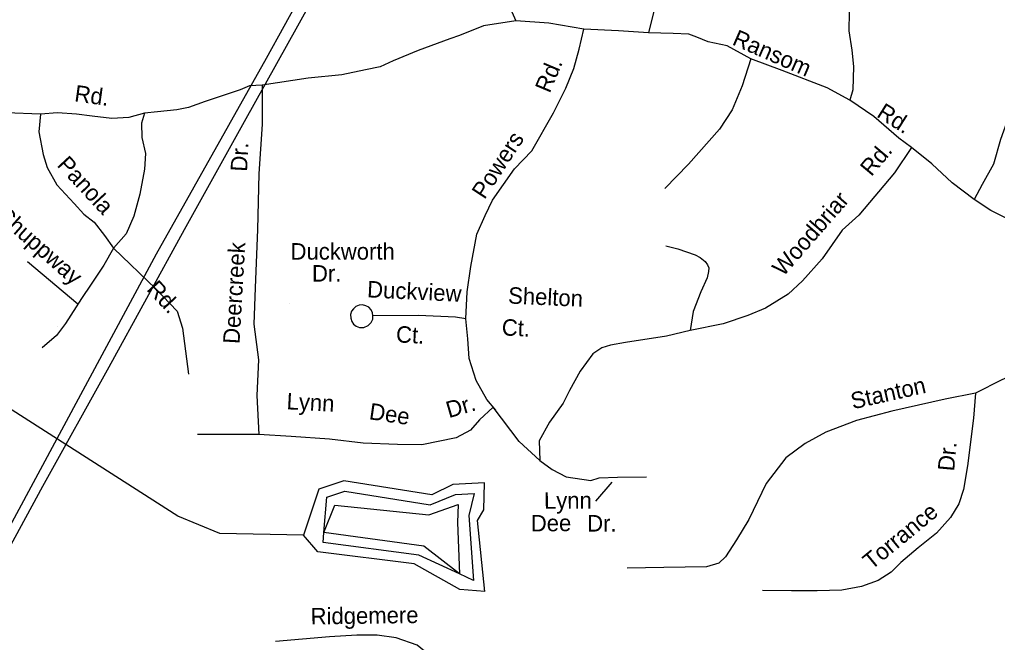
# Model space of a CAD drawing. Extents: x 1551653 to 1702041, y 811336 to 920032.
# Drawn here: x 1610530 to 1614421, y 869748 to 872227 of the extents above; entities that cross this region are included whole.
import ezdxf

# ---------------------------------------------------------------- set-up
doc = ezdxf.new("R2010")
doc.units = 0
for name, color, linetype in [('Old_Level_10', 7, 'Continuous'), ('Old_Level_35', 7, 'Continuous'), ('Old_Level_56', 7, 'Continuous'), ('Old_Level_59', 7, 'Continuous'), ('Old_Level_60', 7, 'Continuous'), ('Old_Level_61', 7, 'Continuous')]:
    doc.layers.add(name, color=color, linetype=linetype)

msp = doc.modelspace()

# ---------------------------------------------------------------- linework, layer by layer
at = {"layer": 'Old_Level_10'}
for p, q in [((1611603.332, 871098.796), (1611603.332, 871098.796)), ((1610680.284, 871003.858), (1610680.284, 871003.858)), ((1612886.473, 870386.234), (1612822.266, 870310.292))]:
    msp.add_line(p, q, dxfattribs=at)
at = {"layer": 'Old_Level_35'}
for p, q in [((1610561.396, 871264.534), (1610762.54, 871095.452)), ((1611481.947, 870576.219), (1611238.347, 870576.219))]:
    msp.add_line(p, q, dxfattribs=at)
for points in [[(1612696.66, 873710.891), (1612676.28, 873663.076), (1612635.886, 873605.461), (1612595.335, 873549.851), (1612572.789, 873494.077), (1612568.537, 873452.138), (1612587.848, 873388.109), (1612637.002, 873305.662), (1612714.285, 873218.841), (1612805.21, 873114.134), (1612913.769, 872971.047), (1612994.688, 872856.335), (1613053.799, 872751.874), (1613094.458, 872625.572), (1613121.564, 872531.366), (1613127.066, 872477.222), (1613110.81, 872435.526), (1613084.304, 872391.638), (1613059.963, 872345.907), (1613053.215, 872259.992), (1613033.074, 872174.752)], [(1613905.739, 872379.958), (1613873.761, 872372.203), (1613857.518, 872360.526), (1613835.336, 872322.754), (1613830.595, 872256.809), (1613829.893, 872182.78), (1613841.313, 872104.703), (1613848.62, 872040.717), (1613845.71, 871946.718), (1613833.238, 871906.48)], [(1612463.113, 872316.053), (1612504.818, 872222.195)], [(1612504.818, 872222.195), (1612376.121, 872201.792), (1612280.323, 872163.444), (1612242.004, 872149.748), (1612116.904, 872103.506), (1612016.612, 872062.518), (1611964.506, 872038.962), (1611906.442, 872027.535), (1611812.281, 872007.314), (1611678.164, 871993.618), (1611495.609, 871966.557)], [(1612775.42, 872189.191), (1612635.614, 872212.643), (1612504.818, 872222.195)], [(1612305.81, 871036.392), (1612311.47, 871144.025), (1612326.303, 871243.782), (1612349.604, 871373.305), (1612382.904, 871447.676), (1612412.356, 871508.516), (1612500.143, 871633.522), (1612568.058, 871704.31), (1612654.397, 871856.449), (1612703.202, 871953.916), (1612736.001, 872031.695), (1612756.591, 872109.526), (1612775.42, 872189.191)], [(1613033.074, 872174.752), (1612913.153, 872181.99), (1612775.42, 872189.191)], [(1613439.098, 872070.828), (1613346.036, 872122.872), (1613270.475, 872138.509), (1613224.825, 872157.049), (1613192.854, 872169.303), (1613130.869, 872171.763), (1613033.074, 872174.752)], [(1613439.098, 872070.828), (1613404.795, 871963.28), (1613366.029, 871867.61), (1613315.229, 871790.196), (1613192.142, 871651.41), (1613097.316, 871554.278)], [(1613833.238, 871906.48), (1613742.914, 871955.784), (1613565.003, 872024.263), (1613439.098, 872070.828)], [(1611495.609, 871966.557), (1611445.512, 871963.488), (1611408.199, 871947.053), (1611269.112, 871900.949)], [(1611495.609, 871966.557), (1611495.609, 871810.427), (1611481.924, 871613.21), (1611476.449, 871391.34), (1611468.262, 871159.653), (1611462.788, 871014.479), (1611481.624, 870872.521), (1611474.341, 870730.586), (1611481.947, 870576.219)], [(1611269.112, 871900.949), (1611202.8, 871877.682), (1611156.387, 871867.619), (1611079.748, 871859.401), (1611027.218, 871854.077)], [(1614078.347, 871717.98), (1614028.219, 871755.417), (1613929.036, 871840.741), (1613833.238, 871906.48)], [(1610613.498, 871850.074), (1610477.728, 871855.232), (1610437.508, 871845.645), (1610367.354, 871810.448), (1610198.253, 871692.01), (1610083.585, 871613.09), (1610017.184, 871555.803), (1609992.847, 871520.078), (1609973.847, 871422.205), (1609954.723, 871288.514), (1609941.643, 871166.706)], [(1610613.498, 871850.074), (1610606.878, 871780.166), (1610624.056, 871689.963), (1610639.607, 871637.818), (1610678.843, 871569.58), (1610748.167, 871494.931), (1610785.729, 871452.542), (1610827.494, 871420.075), (1610868.856, 871367.805), (1610904.456, 871317.451)], [(1611027.218, 871854.077), (1610965.23, 871836.725), (1610897.12, 871833.306), (1610819.256, 871842.092), (1610757.396, 871850.754), (1610681.444, 871855.297), (1610613.498, 871850.074)], [(1611027.218, 871854.077), (1611015, 871814.103), (1611016.467, 871758.241), (1611031.772, 871694.09), (1611027.313, 871632.145), (1611008.275, 871532.27), (1610985.483, 871444.681), (1610954.849, 871374.862), (1610904.456, 871317.451)], [(1614462.313, 871830.934), (1614433.638, 871749.267), (1614404.639, 871651.597), (1614359.957, 871570.059), (1614328.514, 871511.258)], [(1614078.347, 871717.98), (1614011.323, 871617.562), (1613869.821, 871448.933), (1613803.13, 871388.785), (1613724.194, 871274.387), (1613645.576, 871187.133), (1613588.279, 871134.662), (1613498.69, 871078.649), (1613428.453, 871049.256), (1613330.127, 871016.234), (1613197.909, 870989.502)], [(1614328.514, 871511.258), (1614240.927, 871576.997), (1614159.679, 871653.292), (1614078.347, 871717.98)], [(1615022.892, 871151.026), (1614845.373, 871241.808), (1614701.448, 871310.641), (1614559.262, 871381.547), (1614441.831, 871442.567), (1614394.204, 871467.432), (1614328.514, 871511.258)], [(1610904.456, 871317.451), (1610865.86, 871249.793), (1610815.099, 871174.38), (1610776.707, 871116.726), (1610713.652, 871017.346), (1610677.265, 870969.656), (1610620.828, 870920.171)], [(1610904.456, 871317.451), (1611072.463, 871155.337), (1611157.931, 871067.009), (1611178.433, 870998.336), (1611202.031, 870816.009)], [(1613101.095, 871326.467), (1613149.068, 871313.885), (1613218.647, 871291.26), (1613238.031, 871280.059), (1613257.509, 871263.655), (1613267.66, 871251.04), (1613272.21, 871238.74), (1613271.315, 871224.15), (1613265.796, 871198.849), (1613241.452, 871143.107), (1613210.659, 871065.486), (1613197.909, 870989.502)], [(1615075.96, 871124.889), (1614970.448, 871058.588), (1614786.415, 870965.275), (1614651.236, 870886.662), (1614438.405, 870792.725), (1614332.91, 870740.713)], [(1611936.246, 871048.511), (1611934.674, 871059.748), (1611928.913, 871071.674), (1611919.517, 871082.067), (1611908.034, 871088.104), (1611894.688, 871091.178), (1611881.463, 871090.247), (1611868.553, 871085.105), (1611858.366, 871076.306), (1611851.354, 871066.044), (1611847.289, 871053.117), (1611847.998, 871038.695), (1611851.935, 871025.608), (1611859.324, 871015.05), (1611869.766, 871007.035), (1611883.47, 871001.953), (1611900.482, 871002.008), (1611916.83, 871008.879), (1611928.88, 871020.844), (1611935.367, 871034.718), (1611936.246, 871048.511)], [(1612305.81, 871036.392), (1612265.107, 871042.396), (1612117.374, 871049.801), (1611936.246, 871048.511)], [(1612425.285, 870672.041), (1612389.724, 870714.387), (1612346.866, 870789.871), (1612319.087, 870878.25), (1612313.871, 870956.402), (1612305.81, 871036.392)], [(1613197.909, 870989.502), (1613103.785, 870966.398), (1612941.601, 870942.078), (1612881.535, 870930.69), (1612847.52, 870920.972), (1612811.417, 870897.291), (1612760.774, 870827.678), (1612717.979, 870750.303), (1612693.553, 870700.369), (1612638.993, 870625.031)], [(1614332.91, 870740.713), (1614212.737, 870715.94), (1614000.444, 870668.02), (1613860.218, 870631.245), (1613737.797, 870584.503), (1613655.435, 870539.345), (1613579.027, 870482.065), (1613500.127, 870380.806), (1613431.58, 870237.512), (1613382.099, 870156.069), (1613339.5, 870088.493), (1613312.191, 870064.031), (1613263.26, 870049.218), (1613093.316, 870046.866), (1612947.378, 870044.225)], [(1614332.91, 870740.713), (1614326.076, 870640.792), (1614302.215, 870451.166), (1614285.499, 870357.249), (1614266.916, 870299.592), (1614234.407, 870245.819), (1614177.884, 870182.328), (1614105.483, 870125.166), (1614036.838, 870065.724), (1613998.452, 870028.08), (1613946.346, 869994.717), (1613880.031, 869971.249), (1613802.078, 869956.023), (1613703.961, 869953.015), (1613602.121, 869953.881), (1613486.278, 869955.036)], [(1612415.127, 870684.138), (1612360.691, 870634.613), (1612324.97, 870592.653), (1612267.491, 870562.523), (1612130.24, 870534.484), (1612034.207, 870535.435), (1611897.984, 870540.609), (1611763.867, 870557.045), (1611610.59, 870568.001), (1611481.947, 870576.219)], [(1612599.782, 870471.622), (1612518.493, 870547.549), (1612415.127, 870684.138)], [(1612638.993, 870625.031), (1612597.073, 870550.261), (1612599.782, 870471.622)], [(1612599.782, 870471.622), (1612649.97, 870436.057), (1612705.623, 870407.507), (1612803.005, 870392.984), (1612835.804, 870403.302), (1612908.71, 870406.426), (1613024.593, 870407.275)], [(1612223.515, 869607.628), (1612197.463, 869643.862), (1612156.537, 869700.811), (1612112.814, 869737.269), (1612029.011, 869766.437), (1611952.495, 869777.374), (1611872.336, 869777.374), (1611763.028, 869770.083), (1611548.055, 869751.853)]]:
    msp.add_lwpolyline(points, dxfattribs=at)
at = {"layer": 'Old_Level_56'}
for points in [[(1607496.713, 864655.656), (1607618.042, 864875.718), (1607782.474, 865168.949), (1607967.68, 865499.779), (1608185.226, 865875.975), (1608335.534, 866153.485), (1608411.83, 866294.216), (1608557.771, 866553.802), (1608654.073, 866714.136), (1608750.861, 866888.473), (1608840.448, 867064.237), (1608925.254, 867234.801), (1609051.723, 867471.176), (1609288.534, 867908.429), (1609594.56, 868462.745), (1609945.554, 869112.606), (1610266.157, 869714.655), (1610623.269, 870370.396), (1610886.26, 870845.339), (1611186.319, 871391.575), (1611424.97, 871820.783), (1611637.033, 872202.305), (1611863.43, 872609.551)], [(1611793.237, 872582.36), (1611511.712, 872071.773), (1611073.255, 871293.012), (1610687.471, 870575.615), (1610413.991, 870066.866), (1610034.376, 869377.36), (1609728.428, 868817.039), (1609383.445, 868177.26), (1609104.043, 867672.632), (1608883.485, 867257.262), (1608784.13, 867059.62), (1608666.225, 866839.76), (1608485.222, 866518.851), (1608335.563, 866273.35), (1608166.886, 865968.2), (1607963.635, 865625.73), (1607817.733, 865368.145), (1607655.059, 865072.88), (1607523.652, 864849.219), (1607455.801, 864720.322)]]:
    msp.add_lwpolyline(points, dxfattribs=at)
at = {"layer": 'Old_Level_59'}
msp.add_lwpolyline([(1611659.753, 870175.015), (1611326.748, 870181.782), (1611160.759, 870250.782), (1610267.757, 870820.417), (1609653.728, 871062.686), (1608892.678, 871455.668), (1608594.737, 871642.266), (1608330.732, 871887.303)], dxfattribs=at)
at = {"layer": 'Old_Level_60'}
for points in [[(1612254.712, 870376.377), (1612170.743, 870335.366), (1611820.719, 870391.653), (1611720.756, 870357.614), (1611659.753, 870175.015)], [(1612381.741, 869950.278), (1612352.726, 870233.148), (1612377.743, 870275.388), (1612379.691, 870383.656), (1612254.712, 870376.377)], [(1612381.741, 869950.278), (1612281.676, 869958.89), (1612099.692, 870061.006), (1611717.68, 870108.271), (1611659.753, 870175.015)]]:
    msp.add_lwpolyline(points, dxfattribs=at)
at = {"layer": 'Old_Level_61'}
for points in [[(1611737.878, 870146.103), (1611741.056, 870185.268), (1611752.436, 870326.139), (1611824.205, 870350.54), (1612164.386, 870295.894), (1612265.067, 870336.904), (1612338.885, 870341.21), (1612318.278, 870253.55), (1612337.04, 869994.262), (1612280.343, 870020.714), (1612119.275, 870095.865), (1611737.878, 870146.103)], [(1611741.056, 870185.268), (1611784.117, 870294.663), (1612158.029, 870256.421), (1612275.422, 870297.431), (1612273.166, 870224.946), (1612280.343, 870020.714), (1612138.857, 870130.724), (1611741.056, 870185.268)]]:
    msp.add_lwpolyline(points, dxfattribs=at)

# ---------------------------------------------------------------- texts
at = {"layer": 'Old_Level_10'}
for s, rotation, p in [('Ransom', 336.425317, (1613361.905, 872128.852)), ('Rd.', 67.135344, (1612639.372, 871931.069)), ('Rd.', 352.029494, (1610746.184, 871902.093)), ('Rd.', 327.704036, (1613936.527, 871842.587)), ('Powers', 56.839828, (1612380.259, 871508.168)), ('Dr.', 87.025769, (1611435.279, 871620.566)), ('Rd.', 49.955272, (1613919.171, 871599.7)), ('Panola', 312.881897, (1610676.318, 871646.116)), ('Woodbriar', 48.891547, (1613568.433, 871201.259)), ('Chuppway', 318.482108, (1610433.288, 871440.692)), ('Deercreek', 86.702942, (1611405.387, 870934.851)), ('Rd.', 312.881897, (1611032.919, 871151.392)), ('Duckview', 357.13055, (1611912.042, 871121.73)), ('Shelton', 357.358658, (1612473.094, 871097.124)), ('Ct.', 357.358658, (1612447.761, 870970.068)), ('Ct.', 357.13055, (1612026.924, 870942.388)), ('Stanton', 12.719925, (1613845.724, 870675.562)), ('Lynn', 356.979508, (1611591.494, 870676.023)), ('Dee', 351.659297, (1611918.393, 870636.683)), ('Dr.', 16.142914, (1612238.355, 870640.485)), ('Dr.', 84.878119, (1614248.522, 870427.76)), ('Lynn', 0.326672, (1612617.027, 870280.012)), ('Torrance', 39.449614, (1613919.48, 870034.467)), ('Dee', 0.502475, (1612564.654, 870189.566)), ('Dr.', 359.871236, (1612788.636, 870189.475)), ('Ridgemere', 0.774772, (1611688.846, 869819.474))]:
    msp.add_text(s, height=65.6167, rotation=rotation, dxfattribs=at).set_placement(p)
for s, p in [('Duckworth', (1611608.643, 871271.567)), ('Dr.', (1611693.789, 871184.155))]:
    msp.add_text(s, height=65.6167, dxfattribs=at).set_placement(p)

doc.saveas('drawing.dxf')
